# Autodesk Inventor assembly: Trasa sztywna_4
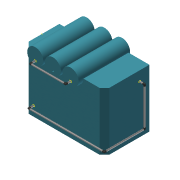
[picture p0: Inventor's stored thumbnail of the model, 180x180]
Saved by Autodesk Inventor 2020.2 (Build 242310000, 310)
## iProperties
Created: 2014-07
Part Number: Trasa sztywna_4
Document SubType Name: Assembly
Designer: F.Stasiak
Catalog Web Link: www.expertbooks.pl
Manager: www.cadconsulting.pl
Company: Fabian Stasiak CAD Consulting
Author: F.Stasiak
Subject: Zbiór ćwiczeń. Autodesk Inventor 2020. Kurs Professional
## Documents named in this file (3)
- C:\2020_Kurs_Professional\R1 Rury\Trasa sztywna_4.iam
- C:\2020_Kurs_Professional\R1 Rury\Konstrukcja_4.ipt
- C:\2020_Kurs_Professional\R1 Rury\Trasa sztywna_4\AIP\Przewody rurowe\Trasa sztywna_4.Przebiegi przewodów rurowych.iam
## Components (2 placed, 2 different names)
1. Konstrukcja_4:1
2. Przebiegi przewodów rurowych [sub-assembly]
